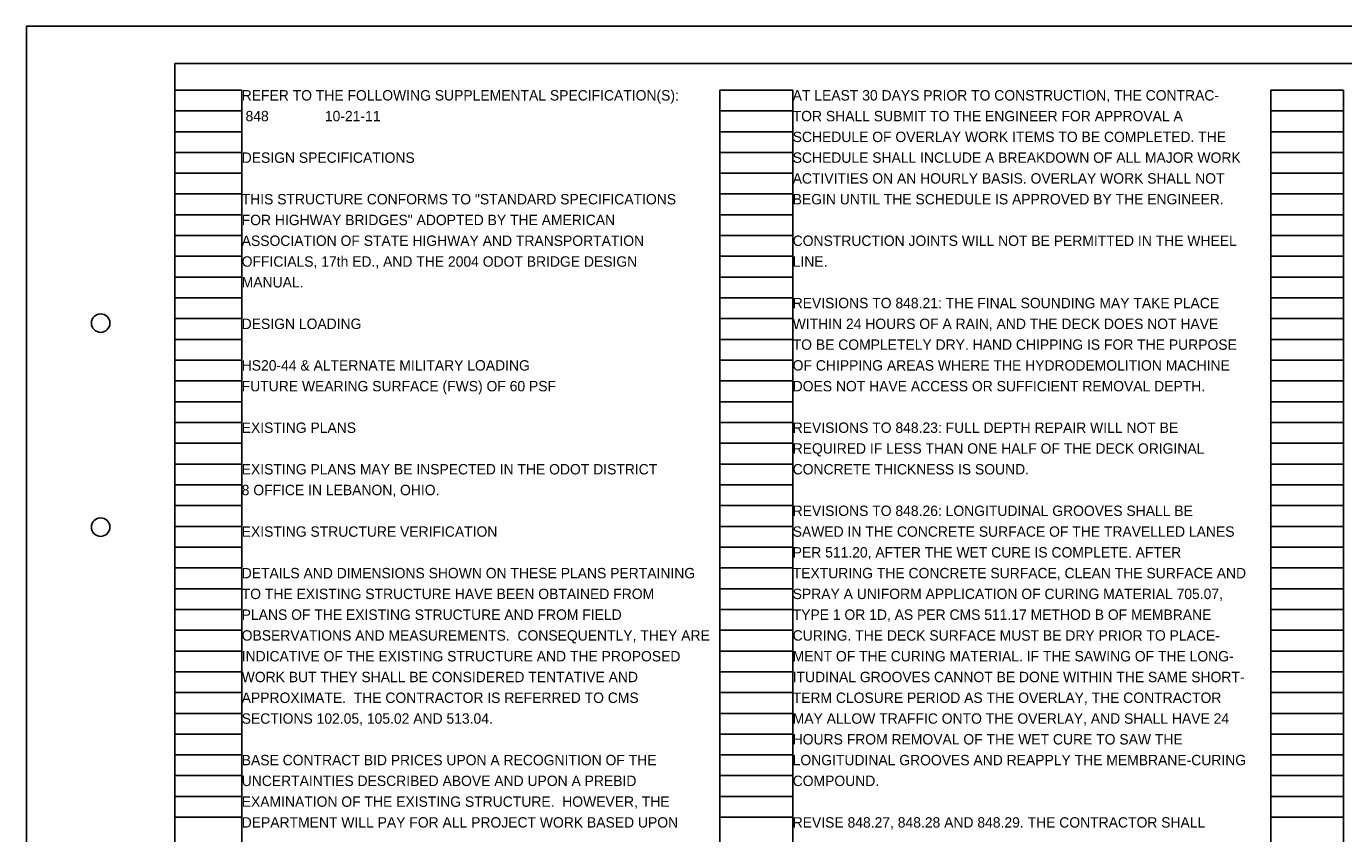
# Model space of a CAD drawing. Extents: x -17.7 to 16.3, y -7.1 to 14.9.
# Drawn here: x -17.72 to 0.02, y 4.06 to 14.95 of the extents above; entities that cross this region are included whole.
import ezdxf

# ---------------------------------------------------------------- set-up
doc = ezdxf.new("R2010")
doc.units = 0
for name, color, linetype in [('BR_P_Gen_Text', 7, 'Continuous'), ('BR_X_Slab_Text', 7, 'Continuous'), ('SH_Border', 7, 'Continuous'), ('SH_Cut_Line', 7, 'Continuous'), ('SH_Data', 7, 'Continuous'), ('SH_Text', 7, 'Continuous')]:
    doc.layers.add(name, color=color, linetype=linetype)

msp = doc.modelspace()

# ---------------------------------------------------------------- linework, layer by layer
at = {"layer": 'SH_Border'}
msp.add_lwpolyline([(-15.715, 14.446), (15.785, 14.446), (15.785, -6.554), (-15.715, -6.554)], close=True, dxfattribs=at)
for centre in [(-16.715, 10.946), (-16.715, 8.196)]:
    msp.add_circle(centre, 0.125, dxfattribs=at)
at = {"layer": 'SH_Cut_Line'}
msp.add_lwpolyline([(-17.715, -7.054), (16.285, -7.054), (16.285, 14.946), (-17.715, 14.946)], close=True, dxfattribs=at)
at = {"layer": 'SH_Data'}
for p, q in [((-15.715, -6.074), (-15.715, 14.086)), ((-15.715, 14.086), (-14.815, 14.086)), ((-14.815, -6.074), (-14.815, 14.086)), ((-8.375, -6.074), (-8.375, 14.086)), ((-8.375, 14.086), (-7.395, 14.086)), ((-7.395, -6.074), (-7.395, 14.086)), ((-0.955, -6.074), (-0.955, 14.086)), ((-0.955, 14.086), (0.025, 14.086)), ((0.025, -6.074), (0.025, 14.086)), ((-15.715, 13.806), (-14.815, 13.806)), ((-8.375, 13.806), (-7.395, 13.806)), ((-0.955, 13.806), (0.025, 13.806)), ((-15.715, 13.526), (-14.815, 13.526)), ((-8.375, 13.526), (-7.395, 13.526)), ((-0.955, 13.526), (0.025, 13.526)), ((-15.715, 13.246), (-14.815, 13.246)), ((-8.375, 13.246), (-7.395, 13.246)), ((-0.955, 13.246), (0.025, 13.246)), ((-15.715, 12.966), (-14.815, 12.966)), ((-8.375, 12.966), (-7.395, 12.966)), ((-0.955, 12.966), (0.025, 12.966)), ((-15.715, 12.686), (-14.815, 12.686)), ((-8.375, 12.686), (-7.395, 12.686)), ((-0.955, 12.686), (0.025, 12.686)), ((-15.715, 12.406), (-14.815, 12.406)), ((-8.375, 12.406), (-7.395, 12.406)), ((-0.955, 12.406), (0.025, 12.406)), ((-15.715, 12.126), (-14.815, 12.126)), ((-8.375, 12.126), (-7.395, 12.126)), ((-0.955, 12.126), (0.025, 12.126)), ((-15.715, 11.846), (-14.815, 11.846)), ((-8.375, 11.846), (-7.395, 11.846)), ((-0.955, 11.846), (0.025, 11.846)), ((-15.715, 11.566), (-14.815, 11.566)), ((-8.375, 11.566), (-7.395, 11.566)), ((-0.955, 11.566), (0.025, 11.566)), ((-15.715, 11.286), (-14.815, 11.286)), ((-8.375, 11.286), (-7.395, 11.286)), ((-0.955, 11.286), (0.025, 11.286)), ((-15.715, 11.006), (-14.815, 11.006)), ((-8.375, 11.006), (-7.395, 11.006)), ((-0.955, 11.006), (0.025, 11.006)), ((-15.715, 10.726), (-14.815, 10.726)), ((-8.375, 10.726), (-7.395, 10.726)), ((-0.955, 10.726), (0.025, 10.726)), ((-15.715, 10.446), (-14.815, 10.446)), ((-8.375, 10.446), (-7.395, 10.446)), ((-0.955, 10.446), (0.025, 10.446)), ((-15.715, 10.166), (-14.815, 10.166)), ((-8.375, 10.166), (-7.395, 10.166)), ((-0.955, 10.166), (0.025, 10.166)), ((-15.715, 9.886), (-14.815, 9.886)), ((-8.375, 9.886), (-7.395, 9.886)), ((-0.955, 9.886), (0.025, 9.886)), ((-15.715, 9.606), (-14.815, 9.606)), ((-8.375, 9.606), (-7.395, 9.606)), ((-0.955, 9.606), (0.025, 9.606)), ((-15.715, 9.326), (-14.815, 9.326)), ((-8.375, 9.326), (-7.395, 9.326)), ((-0.955, 9.326), (0.025, 9.326)), ((-15.715, 9.046), (-14.815, 9.046)), ((-8.375, 9.046), (-7.395, 9.046)), ((-0.955, 9.046), (0.025, 9.046)), ((-15.715, 8.766), (-14.815, 8.766)), ((-8.375, 8.766), (-7.395, 8.766)), ((-0.955, 8.766), (0.025, 8.766)), ((-15.715, 8.486), (-14.815, 8.486)), ((-8.375, 8.486), (-7.395, 8.486)), ((-0.955, 8.486), (0.025, 8.486)), ((-15.715, 8.206), (-14.815, 8.206)), ((-8.375, 8.206), (-7.395, 8.206)), ((-0.955, 8.206), (0.025, 8.206)), ((-15.715, 7.926), (-14.815, 7.926)), ((-8.375, 7.926), (-7.395, 7.926)), ((-0.955, 7.926), (0.025, 7.926)), ((-15.715, 7.646), (-14.815, 7.646)), ((-8.375, 7.646), (-7.395, 7.646)), ((-0.955, 7.646), (0.025, 7.646)), ((-15.715, 7.366), (-14.815, 7.366)), ((-8.375, 7.366), (-7.395, 7.366)), ((-0.955, 7.366), (0.025, 7.366)), ((-15.715, 7.086), (-14.815, 7.086)), ((-8.375, 7.086), (-7.395, 7.086)), ((-0.955, 7.086), (0.025, 7.086)), ((-15.715, 6.806), (-14.815, 6.806)), ((-8.375, 6.806), (-7.395, 6.806)), ((-0.955, 6.806), (0.025, 6.806)), ((-15.715, 6.526), (-14.815, 6.526)), ((-8.375, 6.526), (-7.395, 6.526)), ((-0.955, 6.526), (0.025, 6.526)), ((-15.715, 6.246), (-14.815, 6.246)), ((-8.375, 6.246), (-7.395, 6.246)), ((-0.955, 6.246), (0.025, 6.246)), ((-15.715, 5.966), (-14.815, 5.966)), ((-8.375, 5.966), (-7.395, 5.966)), ((-0.955, 5.966), (0.025, 5.966)), ((-15.715, 5.686), (-14.815, 5.686)), ((-8.375, 5.686), (-7.395, 5.686)), ((-0.955, 5.686), (0.025, 5.686)), ((-15.715, 5.406), (-14.815, 5.406)), ((-8.375, 5.406), (-7.395, 5.406)), ((-0.955, 5.406), (0.025, 5.406)), ((-15.715, 5.126), (-14.815, 5.126)), ((-8.375, 5.126), (-7.395, 5.126)), ((-0.955, 5.126), (0.025, 5.126)), ((-15.715, 4.846), (-14.815, 4.846)), ((-8.375, 4.846), (-7.395, 4.846)), ((-0.955, 4.846), (0.025, 4.846)), ((-15.715, 4.566), (-14.815, 4.566)), ((-8.375, 4.566), (-7.395, 4.566)), ((-0.955, 4.566), (0.025, 4.566)), ((-15.715, 4.286), (-14.815, 4.286)), ((-8.375, 4.286), (-7.395, 4.286)), ((-0.955, 4.286), (0.025, 4.286))]:
    msp.add_line(p, q, dxfattribs=at)

# ---------------------------------------------------------------- texts
at = {"layer": 'BR_P_Gen_Text'}
for s, p in [('REFER TO THE FOLLOWING SUPPLEMENTAL SPECIFICATION(S):', (-14.815, 13.946)), ('DESIGN SPECIFICATIONS', (-14.815, 13.106)), ('DESIGN LOADING', (-14.815, 10.866)), ('EXISTING PLANS', (-14.815, 9.466)), ('EXISTING STRUCTURE VERIFICATION', (-14.815, 8.066))]:
    msp.add_text(s, height=0.14, dxfattribs=at).set_placement(p)
at = {"layer": 'BR_X_Slab_Text'}
for s, p in [('AT LEAST 30 DAYS PRIOR TO CONSTRUCTION, THE CONTRAC-', (-7.395, 13.946)), ('TOR SHALL SUBMIT TO THE ENGINEER FOR APPROVAL A ', (-7.395, 13.666)), ('SCHEDULE OF OVERLAY WORK ITEMS TO BE COMPLETED. THE ', (-7.395, 13.386)), ('SCHEDULE SHALL INCLUDE A BREAKDOWN OF ALL MAJOR WORK ', (-7.395, 13.106)), ('ACTIVITIES ON AN HOURLY BASIS. OVERLAY WORK SHALL NOT', (-7.395, 12.826)), ('BEGIN UNTIL THE SCHEDULE IS APPROVED BY THE ENGINEER.', (-7.395, 12.546)), ('CONSTRUCTION JOINTS WILL NOT BE PERMITTED IN THE WHEEL', (-7.395, 11.986)), ('LINE. ', (-7.395, 11.706)), ('REVISIONS TO 848.21: THE FINAL SOUNDING MAY TAKE PLACE', (-7.395, 11.146)), ('WITHIN 24 HOURS OF A RAIN, AND THE DECK DOES NOT HAVE', (-7.395, 10.866)), ('TO BE COMPLETELY DRY. HAND CHIPPING IS FOR THE PURPOSE', (-7.395, 10.586)), ('OF CHIPPING AREAS WHERE THE HYDRODEMOLITION MACHINE', (-7.395, 10.306)), ('DOES NOT HAVE ACCESS OR SUFFICIENT REMOVAL DEPTH. ', (-7.395, 10.026)), ('REVISIONS TO 848.23: FULL DEPTH REPAIR WILL NOT BE', (-7.395, 9.466)), ('REQUIRED IF LESS THAN ONE HALF OF THE DECK ORIGINAL', (-7.395, 9.186)), ('CONCRETE THICKNESS IS SOUND.', (-7.395, 8.906)), ('REVISIONS TO 848.26: LONGITUDINAL GROOVES SHALL BE', (-7.395, 8.346)), ('SAWED IN THE CONCRETE SURFACE OF THE TRAVELLED LANES', (-7.395, 8.066)), ('PER 511.20, AFTER THE WET CURE IS COMPLETE. AFTER ', (-7.395, 7.786)), ('TEXTURING THE CONCRETE SURFACE, CLEAN THE SURFACE AND', (-7.395, 7.506)), ('SPRAY A UNIFORM APPLICATION OF CURING MATERIAL 705.07, ', (-7.395, 7.226)), ('TYPE 1 OR 1D, AS PER CMS 511.17 METHOD B OF MEMBRANE ', (-7.395, 6.946)), ('CURING. THE DECK SURFACE MUST BE DRY PRIOR TO PLACE-', (-7.395, 6.666)), ('MENT OF THE CURING MATERIAL. IF THE SAWING OF THE LONG-', (-7.395, 6.386)), ('ITUDINAL GROOVES CANNOT BE DONE WITHIN THE SAME SHORT-', (-7.395, 6.106)), ('TERM CLOSURE PERIOD AS THE OVERLAY, THE CONTRACTOR ', (-7.395, 5.826)), ('MAY ALLOW TRAFFIC ONTO THE OVERLAY, AND SHALL HAVE 24 ', (-7.395, 5.546)), ('HOURS FROM REMOVAL OF THE WET CURE TO SAW THE ', (-7.395, 5.266)), ('LONGITUDINAL GROOVES AND REAPPLY THE MEMBRANE-CURING ', (-7.395, 4.986)), ('COMPOUND.', (-7.395, 4.706)), ('REVISE 848.27, 848.28 AND 848.29. THE CONTRACTOR SHALL ', (-7.395, 4.146))]:
    msp.add_text(s, height=0.14, dxfattribs=at).set_placement(p)
at = {"layer": 'SH_Text'}
for s, p in [(' 848', (-14.815, 13.666)), ('10-21-11', (-13.695, 13.666)), ('THIS STRUCTURE CONFORMS TO "STANDARD SPECIFICATIONS', (-14.815, 12.546)), ('FOR HIGHWAY BRIDGES" ADOPTED BY THE AMERICAN', (-14.815, 12.266)), ('ASSOCIATION OF STATE HIGHWAY AND TRANSPORTATION', (-14.815, 11.986)), ('OFFICIALS, 17th ED., AND THE 2004 ODOT BRIDGE DESIGN', (-14.815, 11.706)), ('MANUAL.', (-14.815, 11.426)), ('HS20-44 & ALTERNATE MILITARY LOADING', (-14.815, 10.306)), ('FUTURE WEARING SURFACE (FWS) OF 60 PSF', (-14.815, 10.026)), ('EXISTING PLANS MAY BE INSPECTED IN THE ODOT DISTRICT', (-14.815, 8.906)), ('8 OFFICE IN LEBANON, OHIO.', (-14.815, 8.626)), ('DETAILS AND DIMENSIONS SHOWN ON THESE PLANS PERTAINING', (-14.815, 7.506)), ('TO THE EXISTING STRUCTURE HAVE BEEN OBTAINED FROM', (-14.815, 7.226)), ('PLANS OF THE EXISTING STRUCTURE AND FROM FIELD', (-14.815, 6.946)), ('OBSERVATIONS AND MEASUREMENTS.  CONSEQUENTLY, THEY ARE', (-14.815, 6.666)), ('INDICATIVE OF THE EXISTING STRUCTURE AND THE PROPOSED', (-14.815, 6.386)), ('WORK BUT THEY SHALL BE CONSIDERED TENTATIVE AND', (-14.815, 6.106)), ('APPROXIMATE.  THE CONTRACTOR IS REFERRED TO CMS', (-14.815, 5.826)), ('SECTIONS 102.05, 105.02 AND 513.04.', (-14.815, 5.546)), ('BASE CONTRACT BID PRICES UPON A RECOGNITION OF THE', (-14.815, 4.986)), ('UNCERTAINTIES DESCRIBED ABOVE AND UPON A PREBID', (-14.815, 4.706)), ('EXAMINATION OF THE EXISTING STRUCTURE.  HOWEVER, THE', (-14.815, 4.426)), ('DEPARTMENT WILL PAY FOR ALL PROJECT WORK BASED UPON', (-14.815, 4.146))]:
    msp.add_text(s, height=0.14, dxfattribs=at).set_placement(p)

doc.saveas('drawing.dxf')
